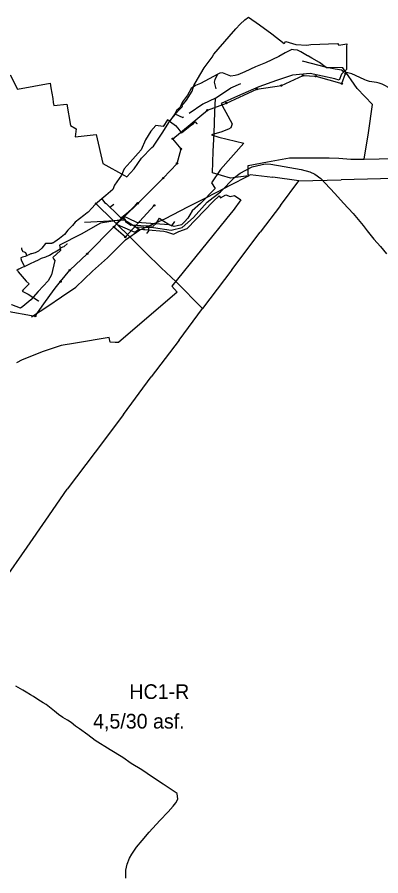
# Model space of a CAD drawing. Extents: x -543464 to -538545, y -1098769 to -1093672.
# Drawn here: x -540988 to -540442, y -1097446 to -1096158 of the extents above; entities that cross this region are included whole.
import ezdxf

# ---------------------------------------------------------------- set-up
doc = ezdxf.new("R2010")
doc.units = 0
for name, color, linetype in [('01_OBVOD PÚ', 7, 'Continuous'), ('03_PC_NAVRH', 7, 'Continuous'), ('03_PC_POPIS_NAVRH', 7, 'Continuous'), ('07_ELEKTRO', 7, 'Continuous'), ('07_KANALIZACE', 7, 'Continuous'), ('07_SDĚLOVACÍ', 7, 'Continuous'), ('07_VODOVOD', 7, 'Continuous')]:
    doc.layers.add(name, color=color, linetype=linetype)

msp = doc.modelspace()

# ---------------------------------------------------------------- linework, layer by layer
at = {"layer": '01_OBVOD PÚ'}
for p, q in [((-540659.7, -1096175.3), (-540653, -1096168.1)), ((-540653, -1096168.1), (-540646.2, -1096161.5)), ((-540646.2, -1096161.5), (-540640.4, -1096157.7)), ((-540640.4, -1096157.7), (-540624.2, -1096169.2)), ((-540685.9, -1096205.7), (-540659.7, -1096175.3)), ((-540624.2, -1096169.2), (-540605.5, -1096182.5)), ((-540605.5, -1096182.5), (-540587, -1096197.4)), ((-540587, -1096197.4), (-540584.7, -1096194.2)), ((-540584.7, -1096194.2), (-540569.4, -1096198.7)), ((-540692.6, -1096213.4), (-540685.9, -1096205.7)), ((-540569.4, -1096198.7), (-540553.1, -1096199.6)), ((-540553.1, -1096199.6), (-540547.2, -1096198.9)), ((-540547.2, -1096198.9), (-540507.2, -1096197)), ((-540507.2, -1096197), (-540505.1, -1096199.6)), ((-540505.1, -1096199.6), (-540493, -1096197.7)), ((-540493, -1096197.7), (-540493.5, -1096201.6)), ((-540493.5, -1096201.6), (-540493.4, -1096205.7)), ((-540493.4, -1096205.7), (-540493.4, -1096230.2)), ((-540706.9, -1096233.8), (-540695.3, -1096217.5)), ((-540695.3, -1096217.5), (-540692.6, -1096213.4)), ((-540493.4, -1096230.2), (-540493.3, -1096236.4)), ((-540998.5, -1096244.4), (-540987.6, -1096265.6)), ((-540717.2, -1096250.8), (-540706.9, -1096233.8)), ((-540574.5, -1096245), (-540598.8, -1096252.7)), ((-540547.8, -1096242.4), (-540574.5, -1096245)), ((-540511.1, -1096250.2), (-540547.8, -1096242.4)), ((-540501.2, -1096243.2), (-540504.4, -1096252.4)), ((-540493.3, -1096236.4), (-540501.2, -1096243.2)), ((-540987.6, -1096265.6), (-540938.3, -1096256.8)), ((-540938.3, -1096256.8), (-540937.2, -1096263.9)), ((-540722.9, -1096260.3), (-540717.2, -1096250.8)), ((-540598.8, -1096252.7), (-540625.1, -1096262.3)), ((-540504.4, -1096252.4), (-540511.1, -1096250.2)), ((-540937.2, -1096263.9), (-540934.5, -1096279.8)), ((-540733.6, -1096282.1), (-540725.1, -1096268.6)), ((-540725.1, -1096268.6), (-540722.9, -1096260.3)), ((-540625.1, -1096262.3), (-540657.3, -1096276.3)), ((-540934.5, -1096279.8), (-540933.6, -1096285.7)), ((-540738.3, -1096287.7), (-540733.6, -1096282.1)), ((-540657.3, -1096276.3), (-540681.6, -1096287.1)), ((-540933.6, -1096285.7), (-540932.8, -1096290.4)), ((-540932.8, -1096290.4), (-540913.2, -1096288.3)), ((-540913.2, -1096288.3), (-540908, -1096320.2)), ((-540746.7, -1096298.7), (-540739.6, -1096291.8)), ((-540740.8, -1096290.7), (-540738.3, -1096287.7)), ((-540739.6, -1096291.8), (-540740.8, -1096290.7)), ((-540681.6, -1096287.1), (-540677, -1096295.7)), ((-540677, -1096295.7), (-540674.4, -1096300.5)), ((-540759.4, -1096314.5), (-540746.7, -1096298.7)), ((-540908, -1096320.2), (-540899.2, -1096325.4)), ((-540770.4, -1096331.6), (-540759.4, -1096314.5)), ((-540899.2, -1096325.4), (-540900.6, -1096337.4)), ((-540900.6, -1096337.4), (-540869.2, -1096333.7)), ((-540869.2, -1096333.7), (-540859.3, -1096377.5)), ((-540783.3, -1096351.1), (-540770.4, -1096331.6)), ((-540695.9, -1096334.2), (-540685.2, -1096337.9)), ((-540685.2, -1096337.9), (-540647.4, -1096347)), ((-540647.4, -1096347), (-540682.6, -1096386.3)), ((-540812.1, -1096385.2), (-540801, -1096369.5)), ((-540859.3, -1096377.5), (-540826.5, -1096395.4)), ((-540823.4, -1096397.2), (-540812.1, -1096385.2)), ((-540682.6, -1096386.3), (-540695.9, -1096406.3)), ((-540826.5, -1096395.4), (-540823.4, -1096397.2)), ((-540695.9, -1096406.3), (-540690.7, -1096414.8)), ((-540690.7, -1096414.8), (-540712.6, -1096437.3)), ((-540693.7, -1096434.1), (-540684.5, -1096426)), ((-540684.5, -1096426), (-540682.6, -1096428.9)), ((-540682.6, -1096428.9), (-540674.8, -1096424.5)), ((-540674.8, -1096424.5), (-540668.3, -1096426.9)), ((-540668.3, -1096426.9), (-540661.6, -1096425.3)), ((-540661.6, -1096425.3), (-540651.9, -1096431.7)), ((-540732.6, -1096474.7), (-540693.7, -1096434.1)), ((-540712.6, -1096437.3), (-540725.4, -1096448.3)), ((-540651.9, -1096431.7), (-540663.4, -1096447.9)), ((-540666.4, -1096451.6), (-540755.6, -1096561.4)), ((-540725.4, -1096448.3), (-540728.9, -1096454.4)), ((-540663.4, -1096447.9), (-540666.4, -1096451.6)), ((-540834.9, -1096463.3), (-540839.5, -1096468.1)), ((-540831.4, -1096459.6), (-540834.9, -1096463.3)), ((-540828.1, -1096456.2), (-540831.4, -1096459.6)), ((-540819.5, -1096460.5), (-540828.1, -1096456.2)), ((-540808.4, -1096466.1), (-540819.5, -1096460.5)), ((-540736.7, -1096464.7), (-540741.3, -1096469.5)), ((-540731.9, -1096459.4), (-540736.7, -1096464.7)), ((-540728.9, -1096454.4), (-540731.9, -1096459.4)), ((-540839.5, -1096468.1), (-540833.4, -1096470.8)), ((-540833.4, -1096470.8), (-540811.4, -1096480.3)), ((-540811.4, -1096480.3), (-540805.1, -1096476)), ((-540759.5, -1096469.2), (-540808.4, -1096466.1)), ((-540805.1, -1096476), (-540798.4, -1096476.4)), ((-540798.4, -1096476.4), (-540796.1, -1096476.5)), ((-540796.1, -1096476.5), (-540791.1, -1096476.8)), ((-540791.1, -1096476.8), (-540767.9, -1096478.8)), ((-540752.1, -1096472.1), (-540759.5, -1096469.2)), ((-540747.5, -1096471), (-540752.1, -1096472.1)), ((-540741.3, -1096469.5), (-540747.5, -1096471)), ((-540745.4, -1096479.6), (-540732.6, -1096474.7)), ((-540767.9, -1096478.8), (-540763.6, -1096480.1)), ((-540763.6, -1096480.1), (-540753.1, -1096483.6)), ((-540753.1, -1096483.6), (-540745.4, -1096479.6)), ((-540755.6, -1096561.4), (-540747.9, -1096570.3)), ((-540747.9, -1096570.3), (-540835.6, -1096645.8)), ((-540849.7, -1096638.2), (-540900.4, -1096647.1)), ((-540848.1, -1096645.6), (-540849.7, -1096638.2)), ((-540840.9, -1096645.7), (-540848.1, -1096645.6)), ((-540835.6, -1096645.8), (-540840.9, -1096645.7)), ((-540921.7, -1096650.7), (-540948.6, -1096659.6)), ((-540900.4, -1096647.1), (-540921.7, -1096650.7)), ((-540948.6, -1096659.6), (-540980.1, -1096671.9)), ((-540980.1, -1096671.9), (-540988.7, -1096676.6))]:
    msp.add_line(p, q, dxfattribs=at)
for points in [[(-540674.4, -1096300.5), (-540665.3, -1096317.7), (-540667.1, -1096323.6), (-540670.4, -1096325.9), (-540682, -1096330.1), (-540687.5, -1096331.9), (-540695.9, -1096334.2)], [(-540801, -1096369.5), (-540785.5, -1096353.3), (-540783.3, -1096351.1)]]:
    msp.add_lwpolyline(points, dxfattribs=at)
at = {"layer": '03_PC_NAVRH'}
for points in [[(-540811.6, -1096472.6), (-540783, -1096473.3), (-540756.9, -1096477.2), (-540740.4, -1096473.6), (-540723.1, -1096458.2), (-540702.8, -1096435.4), (-540682.7, -1096419.7), (-540661.4, -1096398.1), (-540653, -1096391.7), (-540635.1, -1096382.1), (-540615.8, -1096377.9), (-540607.2, -1096378.4), (-540587.1, -1096382), (-540561.3, -1096386.1), (-540548.5, -1096389.7), (-540541.2, -1096393.4), (-540532, -1096399.8), (-540525.3, -1096406.7), (-540511.2, -1096422.4), (-540498.1, -1096437), (-540483.5, -1096452.4), (-540468.7, -1096470.4), (-540462.7, -1096478.3), (-540452.3, -1096491.1), (-540442.4, -1096501.9), (-540433.2, -1096512.9)], [(-540824.6, -1097449.8), (-540824.6, -1097437.7), (-540822.8, -1097429), (-540819, -1097420), (-540815.6, -1097413.9), (-540808.6, -1097403.3), (-540800.1, -1097393.1), (-540789.6, -1097380.6), (-540773.9, -1097363.3), (-540761.1, -1097350.2), (-540753.8, -1097342), (-540749.8, -1097336.8), (-540746.9, -1097331.1), (-540747.6, -1097322.9), (-540768.6, -1097308.9), (-540784.7, -1097298.2), (-540800.7, -1097287.4), (-540816.7, -1097277.6), (-540829.3, -1097268.8), (-540848.3, -1097257), (-540870.7, -1097243), (-540882, -1097234.7), (-540894.5, -1097225.5), (-540900.3, -1097221.6), (-540907, -1097216.4), (-540912.5, -1097212.9), (-540919.2, -1097208.5), (-540925.9, -1097204.1), (-540931.8, -1097199.1), (-540939.2, -1097193.4), (-540944.5, -1097189.3), (-540948.6, -1097186.9), (-540956.8, -1097181.5), (-540963.2, -1097177.3), (-540967.7, -1097174.5), (-540974.1, -1097170.5), (-540979.5, -1097167.5), (-540989.9, -1097161.8)]]:
    msp.add_lwpolyline(points, dxfattribs=at)
at = {"layer": '07_ELEKTRO'}
for points in [[(-540523.2, -1096233), (-540559.7, -1096223.6)], [(-540498.8, -1096233.8), (-540523.2, -1096233)], [(-540477.4, -1096264.6), (-540498.8, -1096233.8)], [(-540667, -1096263.7), (-540652.3, -1096257.1)], [(-540690, -1096279.5), (-540667, -1096263.7)], [(-540454.4, -1096288.7), (-540477.4, -1096264.6)], [(-540690, -1096279.5), (-540709.3, -1096288.1)], [(-540691.1, -1096300.1), (-540690, -1096279.5)], [(-540709.3, -1096288.1), (-540729.5, -1096302.2)], [(-540460.3, -1096331.4), (-540454.4, -1096288.7)], [(-540692.2, -1096331.9), (-540691.1, -1096300.1)], [(-540693.7, -1096359.3), (-540692.2, -1096331.9)], [(-540466.8, -1096371), (-540460.3, -1096331.4)], [(-540694.6, -1096391.3), (-540693.7, -1096359.3)], [(-540640.9, -1096380.2), (-540612.1, -1096375)], [(-540612.1, -1096375), (-540579.1, -1096368.6)], [(-540579.1, -1096368.6), (-540550.7, -1096368.6)], [(-540550.7, -1096368.6), (-540519.6, -1096368.7)], [(-540519.6, -1096368.7), (-540505.2, -1096369.1)], [(-540505.2, -1096369.1), (-540487.2, -1096370.6)], [(-540487.2, -1096370.6), (-540466.8, -1096371)], [(-540466.8, -1096371), (-540422.1, -1096369.9)], [(-540641.1, -1096394.2), (-540640.9, -1096380.2)], [(-540667.7, -1096399.1), (-540694.6, -1096391.3)], [(-540668.3, -1096409.7), (-540640.5, -1096395.8)], [(-540640.5, -1096395.8), (-540667.7, -1096399.1)], [(-540639.2, -1096394.8), (-540641.1, -1096394.2)], [(-540640.5, -1096395.8), (-540639.2, -1096394.8)], [(-540637.9, -1096393.8), (-540603.9, -1096398)], [(-540565, -1096403.5), (-540603.9, -1096398)], [(-540402.9, -1096399.1), (-540501.5, -1096402)], [(-540686.1, -1096419.4), (-540668.3, -1096409.7)], [(-540592.8, -1096440.2), (-540565, -1096403.5)], [(-540565, -1096403.5), (-540501.5, -1096402)], [(-540707.8, -1096430.1), (-540686.1, -1096419.4)], [(-540814.7, -1096491.3), (-540870.6, -1096436.2)], [(-540826.9, -1096462.2), (-540826.5, -1096460.9), (-540826.4, -1096460.1), (-540828.7, -1096457.1), (-540825.2, -1096454.3), (-540819.7, -1096449.2), (-540810.4, -1096439.9), (-540806.6, -1096436), (-540806.3, -1096435.6)], [(-540730.8, -1096441.9), (-540707.8, -1096430.1)], [(-540766.3, -1096460.4), (-540730.8, -1096441.9)], [(-540592.8, -1096440.2), (-540623, -1096480.4)], [(-540858.5, -1096464.3), (-540887, -1096465.7)], [(-540826.9, -1096462.2), (-540858.5, -1096464.3)], [(-540803.8, -1096476.9), (-540826.9, -1096462.2)], [(-540803.8, -1096476.9), (-540766.3, -1096460.4)], [(-540825.1, -1096491.9), (-540803.8, -1096476.9)], [(-540665.4, -1096536.8), (-540623, -1096480.4)], [(-540852.2, -1096519), (-540825.1, -1096491.9)], [(-540795.1, -1096511.1), (-540814.7, -1096491.3)], [(-540771.5, -1096534.1), (-540795.1, -1096511.1)], [(-540874.8, -1096539.1), (-540852.2, -1096519)], [(-540900, -1096563.1), (-540874.8, -1096539.1)], [(-540749.2, -1096555.1), (-540771.5, -1096534.1)], [(-540665.4, -1096536.8), (-540709.6, -1096595)], [(-540709.6, -1096595), (-540749.2, -1096555.1)], [(-540921.4, -1096577.6), (-540900, -1096563.1)], [(-540942, -1096591.5), (-540921.4, -1096577.6)], [(-540966.1, -1096607.4), (-540942, -1096591.5)], [(-540744.6, -1096642.2), (-540709.6, -1096595)], [(-540744.6, -1096642.2), (-540786.8, -1096697.7)], [(-540828.1, -1096753.8), (-540786.8, -1096697.7)], [(-540828.1, -1096753.8), (-540871, -1096810.4)], [(-540871, -1096810.4), (-540913, -1096865.9)], [(-540944.7, -1096912.5), (-540913, -1096865.9)], [(-540972.7, -1096953.3), (-540944.7, -1096912.5)], [(-541008.2, -1097004), (-540972.7, -1096953.3)]]:
    msp.add_lwpolyline(points, dxfattribs=at)
at = {"layer": '07_KANALIZACE'}
for p, q in [((-540591.2, -1096260.3), (-540558.7, -1096245.1)), ((-540558.7, -1096245.1), (-540539.7, -1096246.3)), ((-540539.7, -1096246.3), (-540500.5, -1096257.5)), ((-540500.5, -1096257.5), (-540494.9, -1096242.4)), ((-540673.8, -1096286.6), (-540627.9, -1096265.7)), ((-540627.9, -1096265.7), (-540591.2, -1096260.3)), ((-540754.3, -1096340.1), (-540702.3, -1096297.4)), ((-540702.3, -1096297.4), (-540673.8, -1096286.6)), ((-540741.8, -1096355.3), (-540754.3, -1096340.1)), ((-540747.7, -1096377.1), (-540741.8, -1096355.3)), ((-540768.7, -1096399.3), (-540747.7, -1096377.1)), ((-540806.7, -1096437.3), (-540768.7, -1096399.3)), ((-540842.5, -1096472.5), (-540806.7, -1096437.3)), ((-540825.4, -1096487.6), (-540782.1, -1096440.2)), ((-540882.6, -1096512.8), (-540842.5, -1096472.5)), ((-540842.5, -1096472.5), (-540825.4, -1096487.6)), ((-540908.9, -1096537.4), (-540882.6, -1096512.8)), ((-540922.7, -1096554.5), (-540908.9, -1096537.4)), ((-541005.3, -1096598.3), (-540960.7, -1096606.4))]:
    msp.add_line(p, q, dxfattribs=at)
msp.add_lwpolyline([(-540960.7, -1096606.4), (-540947.7, -1096587.7), (-540939, -1096575.3), (-540930.9, -1096564.2), (-540922.7, -1096554.5)], dxfattribs=at)
for centre in [(-540558.7, -1096245.1), (-540539.7, -1096246.3), (-540494.9, -1096242.4), (-540500.5, -1096257.5), (-540627.9, -1096265.7), (-540591.2, -1096260.3), (-540702.3, -1096297.4), (-540673.8, -1096286.6), (-540754.3, -1096340.1), (-540741.8, -1096355.3), (-540747.7, -1096377.1), (-540768.7, -1096399.3), (-540806.7, -1096437.3), (-540782.1, -1096440.2), (-540842.5, -1096472.5), (-540825.4, -1096487.6), (-540882.6, -1096512.8), (-540908.9, -1096537.4), (-540922.7, -1096554.5), (-540960.7, -1096606.4), (-540960.7, -1096606.4)]:
    msp.add_circle(centre, 1.03, dxfattribs=at)
at = {"layer": '07_SDĚLOVACÍ'}
for points in [[(-540573.1, -1096206.5), (-540575.3, -1096206), (-540585.3, -1096211.1), (-540595, -1096216.7), (-540615, -1096226.3), (-540630.2, -1096232.4), (-540646.1, -1096239.8), (-540656.4, -1096244.1), (-540660.6, -1096245.5), (-540667.1, -1096246.3), (-540679.4, -1096241.1), (-540683.6, -1096241.6), (-540686.6, -1096243.2)], [(-540551.2, -1096215.8), (-540551.8, -1096215.5), (-540561.9, -1096209.5), (-540566.8, -1096207), (-540573.1, -1096206.5)], [(-540550.3, -1096216.4), (-540551.2, -1096215.8)], [(-540521.7, -1096233.9), (-540523.7, -1096233.6), (-540533.8, -1096225.9), (-540545.6, -1096219.4), (-540550.3, -1096216.4)], [(-540686.6, -1096243.2), (-540712.8, -1096257.5), (-540720.1, -1096260.5), (-540726.9, -1096264.6), (-540732.4, -1096274.9), (-540739.7, -1096284.9), (-540743.9, -1096293.8), (-540748, -1096297.5), (-540751.3, -1096302.8)], [(-540686.6, -1096243.2), (-540687.1, -1096243.7), (-540691.3, -1096251.4), (-540691.9, -1096255.4), (-540689.6, -1096265.1)], [(-540518.2, -1096234.3), (-540521.7, -1096233.9)], [(-540510.3, -1096235.6), (-540518.2, -1096234.3)], [(-540510.3, -1096235.6), (-540510.2, -1096235.1)], [(-540500.4, -1096237.2), (-540510.3, -1096235.6)], [(-540500.1, -1096237.9), (-540500.4, -1096237.2)], [(-540500.4, -1096237.2), (-540498.4, -1096237.5)], [(-540499.8, -1096238.3), (-540500.1, -1096237.9)], [(-540422.5, -1096272.5), (-540423.9, -1096269.7), (-540426.2, -1096266.9), (-540431.2, -1096262.9), (-540434.8, -1096260.8), (-540439.7, -1096258.5), (-540444.5, -1096256.8), (-540448.6, -1096255.9), (-540459.1, -1096254.1), (-540463.7, -1096252.7), (-540466.2, -1096251.7), (-540473.7, -1096248.5), (-540485.6, -1096242.9), (-540493.7, -1096240.7), (-540498.7, -1096239.2), (-540499.7, -1096238.6), (-540499.8, -1096238.3)], [(-540485.6, -1096242.9), (-540493.7, -1096240.7), (-540498.7, -1096239.2), (-540499.7, -1096238.6)], [(-540751.3, -1096302.8), (-540758.2, -1096313)], [(-540751.3, -1096302.8), (-540739.2, -1096308.1), (-540738.2, -1096307.2)], [(-540758.7, -1096313.8), (-540759.4, -1096313.1), (-540762.4, -1096311.8), (-540768.9, -1096321.9), (-540779.7, -1096320.5), (-540787, -1096328.7), (-540795.2, -1096341.9), (-540801.8, -1096356.8), (-540806, -1096361.9), (-540818, -1096375.4), (-540827.1, -1096385.2), (-540831, -1096394.8), (-540841.8, -1096409.8), (-540844.3, -1096416.3), (-540854.6, -1096425.1), (-540861, -1096430.1)], [(-540758.2, -1096313), (-540758.7, -1096313.8)], [(-540758.7, -1096313.8), (-540757.8, -1096314.6)], [(-540757.8, -1096314.6), (-540757.6, -1096314.5)], [(-540757.8, -1096314.6), (-540750.2, -1096320.5), (-540746.6, -1096324.2), (-540742.1, -1096330.1), (-540741.1, -1096331.2), (-540728, -1096320.7), (-540723.4, -1096317.2), (-540720.6, -1096315), (-540718.3, -1096317.8), (-540717.4, -1096317.1)], [(-540746.6, -1096324.2), (-540742.1, -1096330.1)], [(-540861, -1096430.1), (-540871, -1096438.9), (-540875.9, -1096444.6), (-540881.3, -1096450.4), (-540882.9, -1096451.6), (-540887.8, -1096455.4), (-540900.8, -1096465.3), (-540904.8, -1096470.6), (-540911.6, -1096477.6), (-540916.7, -1096483.9), (-540924.5, -1096489.9), (-540931.5, -1096495.1), (-540932.7, -1096495.9), (-540935.6, -1096496.7), (-540936.9, -1096497.3), (-540945.3, -1096497.2), (-540950.7, -1096504.3), (-540955.8, -1096508.7), (-540960.7, -1096511.2), (-540966.4, -1096512.7), (-540967.3, -1096513), (-540976, -1096516.7)], [(-540861, -1096430.1), (-540856.9, -1096435.9), (-540854.4, -1096437.4), (-540848.9, -1096443)], [(-540854.4, -1096437.4), (-540848.9, -1096443)], [(-540848.9, -1096443), (-540842.7, -1096438.1)], [(-540848.9, -1096443), (-540841.4, -1096450.1), (-540832.9, -1096458.3)], [(-540831.8, -1096458.8), (-540830.5, -1096457.9), (-540820.8, -1096449.7), (-540815.8, -1096445.6)], [(-540832.9, -1096458.3), (-540832.7, -1096458)], [(-540832.9, -1096458.3), (-540831.8, -1096458.8)], [(-540831.8, -1096458.8), (-540825.6, -1096461.6), (-540825.9, -1096463.6), (-540825.3, -1096464.6), (-540817, -1096469.8), (-540814.6, -1096469.5), (-540802.2, -1096470.4), (-540790.4, -1096471.1)], [(-540825.3, -1096464.6), (-540817, -1096469.8)], [(-540790.4, -1096471.1), (-540783.5, -1096471.4), (-540779, -1096467.4), (-540774.1, -1096459.4), (-540770.1, -1096462.3), (-540758.6, -1096469.6), (-540755.6, -1096470.9), (-540751.3, -1096464.4)], [(-540774.1, -1096459.4), (-540770.1, -1096462.3)], [(-540790.4, -1096471.1), (-540790.5, -1096477), (-540790.8, -1096478.6), (-540793.2, -1096481.9), (-540792.6, -1096482.5)], [(-540790.4, -1096471.1), (-540790.5, -1096477)], [(-540968.8, -1096527.7), (-540960.3, -1096524.1), (-540956.8, -1096522.4), (-540951.3, -1096519.6), (-540945, -1096517.3), (-540939.2, -1096515), (-540933.6, -1096511.4), (-540930.6, -1096509.7), (-540923.3, -1096505.2), (-540922.3, -1096503.7), (-540919.5, -1096502.3)], [(-540935.6, -1096496.7), (-540932.7, -1096495.9)], [(-540919.5, -1096502.3), (-540917.5, -1096501.8), (-540912.6, -1096498.1), (-540912.4, -1096498.4)], [(-540919.5, -1096502.3), (-540918.9, -1096502.9)], [(-540976, -1096516.7), (-540979.8, -1096518), (-540982.5, -1096518.9), (-540981.6, -1096521.9), (-540977.9, -1096529.8), (-540976.9, -1096531.8)], [(-540981.1, -1096504.1), (-540981.2, -1096505.7), (-540979.5, -1096509.6), (-540977.4, -1096509.8), (-540975.1, -1096510.7), (-540973.5, -1096515.9), (-540976, -1096516.7)], [(-540977.9, -1096529.8), (-540981.6, -1096521.9)], [(-540976.9, -1096531.8), (-540968.8, -1096527.7)], [(-540968.8, -1096527.7), (-540968.4, -1096528.6)], [(-540960.3, -1096524.1), (-540956.8, -1096522.4)], [(-540951.3, -1096519.6), (-540945, -1096517.3)], [(-540987.8, -1096537.4), (-540988.8, -1096537.7)], [(-540981.1, -1096533.9), (-540985.4, -1096535.9), (-540987.8, -1096537.4)], [(-540987.8, -1096537.4), (-540987.3, -1096538)], [(-540987.3, -1096538), (-540986.4, -1096539.8), (-540974.3, -1096554), (-540969.6, -1096558.1)], [(-540976.9, -1096531.8), (-540981.1, -1096533.9)], [(-540973.7, -1096561.8), (-540978.7, -1096566.7), (-540980.1, -1096568.9), (-540971.4, -1096573.2), (-540955.6, -1096583.3)], [(-540969.6, -1096558.1), (-540971.9, -1096560), (-540973.7, -1096561.8)], [(-540955.6, -1096583.3), (-540956.4, -1096584.2)]]:
    msp.add_lwpolyline(points, dxfattribs=at)
at = {"layer": '07_VODOVOD'}
for points in [[(-540831.6, -1096461.9), (-540862.6, -1096467.1), (-540891.8, -1096483.3), (-540924.5, -1096500), (-540922.9, -1096507.4), (-540922.7, -1096507.7), (-540934.5, -1096518.5), (-540933.1, -1096520.4)], [(-540933.1, -1096520.4), (-540931.1, -1096523.1), (-540936.3, -1096544.3), (-540941.4, -1096553.5), (-540956.1, -1096569.6), (-540967.4, -1096582.1), (-540979.5, -1096592), (-540982.9, -1096594.3), (-540996.1, -1096589.3), (-540996.2, -1096589.2)]]:
    msp.add_lwpolyline(points, dxfattribs=at)

# ---------------------------------------------------------------- texts
at = {"layer": '03_PC_POPIS_NAVRH'}
for s, p in [('HC1-R', (-540819.4, -1097180.9)), ('4,5/30 asf.', (-540873.9, -1097225.3))]:
    msp.add_text(s, height=22, dxfattribs=at).set_placement(p)

doc.saveas('drawing.dxf')
